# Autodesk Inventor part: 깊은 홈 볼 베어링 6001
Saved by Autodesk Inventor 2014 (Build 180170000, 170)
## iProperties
Created: 2026-08
Part Number: 깊은 홈 볼 베어링 6001
Material: 일반
Document SubType Name: Modeling
Designer: dg
Density: 1 g/cm^3
Appearance: 기본값
Author: dg
Author: jhkim
Description: 깊은 그루브 볼 베어링
Creation Date: 2026-07-31
Sending System: Autodesk Inventor 2027
Preprocessor: ST-DEVELOPER v20.1
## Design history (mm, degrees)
node "깊은 홈 볼 베어링 60011"
body "Solid1"
node "Solid1_1"
node "Solid1_2"
node "Solid1_3"
node "Solid1_4"
node "Solid1_5"
node "Solid1_6"
node "Solid1_7"
node "Solid1_8"
node "Solid1_9"
node "기준1"
node "기준2"
node "기준3"
node "기준4"
node "기준5"
node "기준6"
node "기준7"
node "기준8"
node "기준9"
node "기준10"
